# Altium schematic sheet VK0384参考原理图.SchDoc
size A4
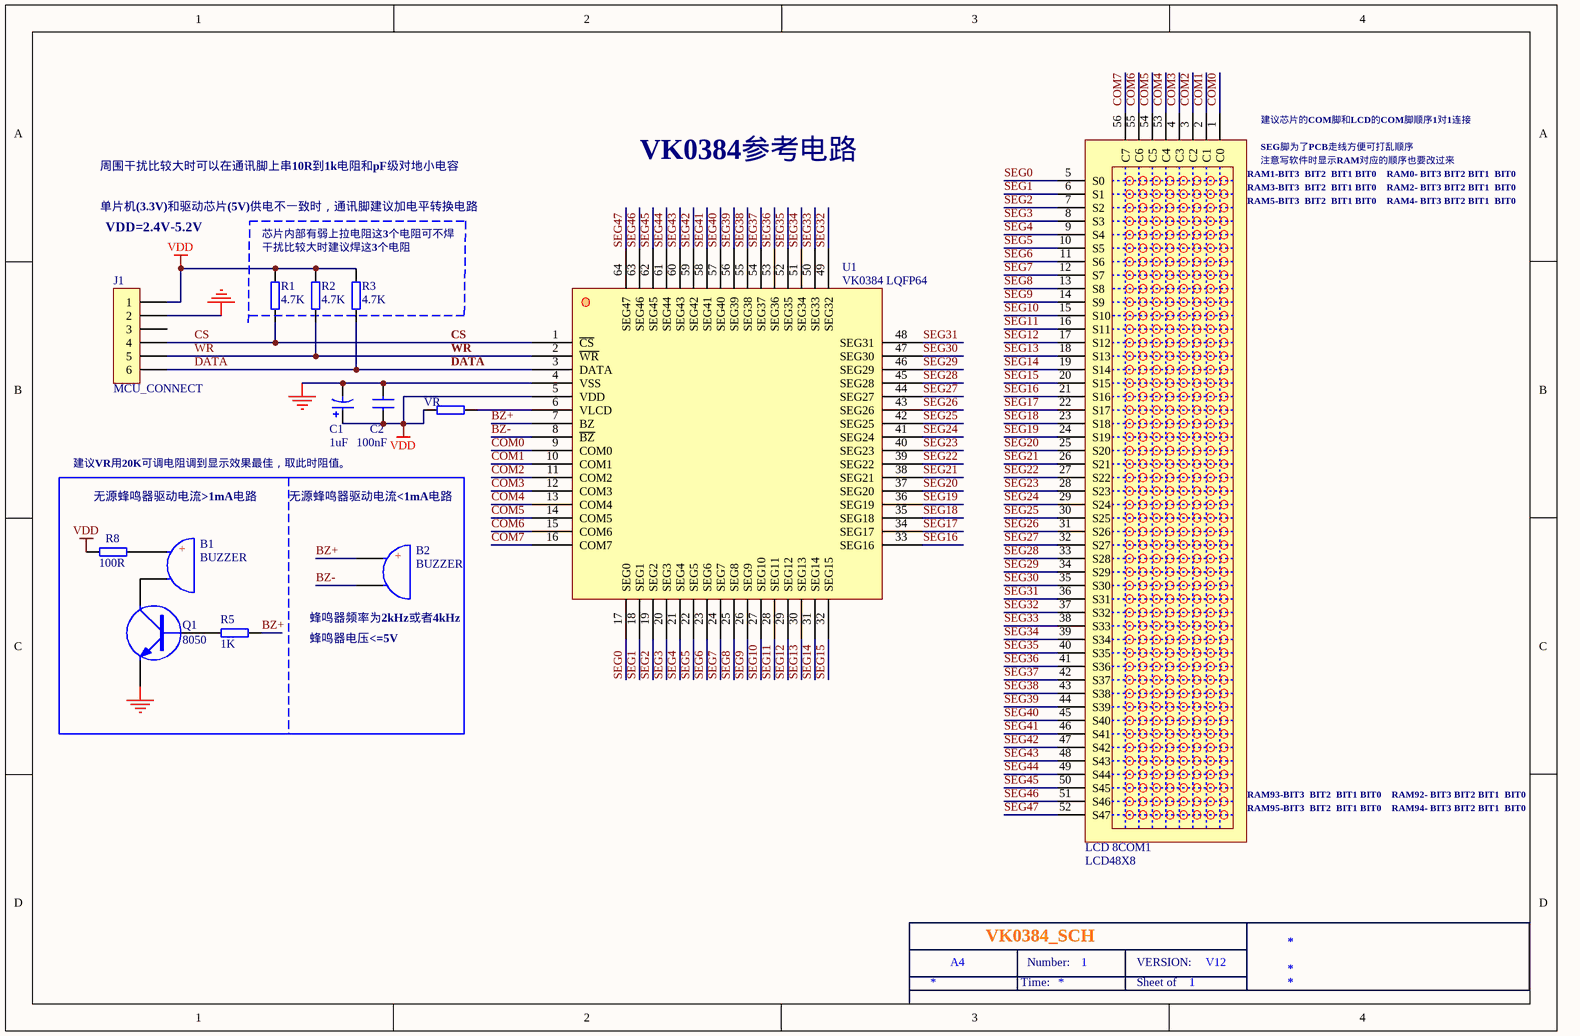
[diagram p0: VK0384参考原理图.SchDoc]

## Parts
B1  BUZZER  [BUZZER-12]
B2  BUZZER  [BUZZER-12]
C1  1uF  [1206-C]
C2  100nF  [0603-C]
J1  MCU_CONNECT
LCD_8COM1  LCD48X8
Q1  8050  [SOT-23]
R1  4.7K  [0603-R]
R2  4.7K  [0603-R]
R3  4.7K  [0603-R]
R5  1K  [0603-R]
R8  100R  [0603-R]
U1  VK0384 LQFP64
VR  (no value)  [0603-R]

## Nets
GND: C1.2 C2.2 J1.2 Q1.2 U1.4(VSS)
VDD: C1.1 C2.1 J1.1 R1.1 R2.1 R3.1 R8.2 U1.5(VDD) VR.1
BZ+: B2.1 R5.2 U1.7(BZ)
BZ-: B2.2 U1.8(~{BZ})
COM0: LCD_8COM1.1(C0) U1.9(COM0)
COM1: LCD_8COM1.2(C1) U1.10(COM1)
COM2: LCD_8COM1.3(C2) U1.11(COM2)
COM3: LCD_8COM1.4(C3) U1.12(COM3)
COM4: LCD_8COM1.53(C4) U1.13(COM4)
COM5: LCD_8COM1.54(C5) U1.14(COM5)
COM6: LCD_8COM1.55(C6) U1.15(COM6)
COM7: LCD_8COM1.56(C7) U1.16(COM7)
CS: J1.4 R1.2 U1.1(~{CS})
DATA: J1.6 R3.2 U1.3(DATA)
SEG0: LCD_8COM1.5(S0) U1.17(SEG0)
SEG1: LCD_8COM1.6(S1) U1.18(SEG1)
SEG2: LCD_8COM1.7(S2) U1.19(SEG2)
SEG3: LCD_8COM1.8(S3) U1.20(SEG3)
SEG4: LCD_8COM1.9(S4) U1.21(SEG4)
SEG5: LCD_8COM1.10(S5) U1.22(SEG5)
SEG6: LCD_8COM1.11(S6) U1.23(SEG6)
SEG7: LCD_8COM1.12(S7) U1.24(SEG7)
SEG8: LCD_8COM1.13(S8) U1.25(SEG8)
SEG9: LCD_8COM1.14(S9) U1.26(SEG9)
SEG10: LCD_8COM1.15(S10) U1.27(SEG10)
SEG11: LCD_8COM1.16(S11) U1.28(SEG11)
SEG12: LCD_8COM1.17(S12) U1.29(SEG12)
SEG13: LCD_8COM1.18(S13) U1.30(SEG13)
SEG14: LCD_8COM1.19(S14) U1.31(SEG14)
SEG15: LCD_8COM1.20(S15) U1.32(SEG15)
SEG16: LCD_8COM1.21(S16) U1.33(SEG16)
SEG17: LCD_8COM1.22(S17) U1.34(SEG17)
SEG18: LCD_8COM1.23(S18) U1.35(SEG18)
SEG19: LCD_8COM1.24(S19) U1.36(SEG19)
SEG20: LCD_8COM1.25(S20) U1.37(SEG20)
SEG21: LCD_8COM1.26(S21) U1.38(SEG21)
SEG22: LCD_8COM1.27(S22) U1.39(SEG22)
SEG23: LCD_8COM1.28(S23) U1.40(SEG23)
SEG24: LCD_8COM1.29(S24) U1.41(SEG24)
SEG25: LCD_8COM1.30(S25) U1.42(SEG25)
SEG26: LCD_8COM1.31(S26) U1.43(SEG26)
SEG27: LCD_8COM1.32(S27) U1.44(SEG27)
SEG28: LCD_8COM1.33(S28) U1.45(SEG28)
SEG29: LCD_8COM1.34(S29) U1.46(SEG29)
SEG30: LCD_8COM1.35(S30) U1.47(SEG30)
SEG31: LCD_8COM1.36(S31) U1.48(SEG31)
SEG32: LCD_8COM1.37(S32) U1.49(SEG32)
SEG33: LCD_8COM1.38(S33) U1.50(SEG33)
SEG34: LCD_8COM1.39(S34) U1.51(SEG34)
SEG35: LCD_8COM1.40(S35) U1.52(SEG35)
SEG36: LCD_8COM1.41(S36) U1.53(SEG36)
SEG37: LCD_8COM1.42(S37) U1.54(SEG37)
SEG38: LCD_8COM1.43(S38) U1.55(SEG38)
SEG39: LCD_8COM1.44(S39) U1.56(SEG39)
SEG40: LCD_8COM1.45(S40) U1.57(SEG40)
SEG41: LCD_8COM1.46(S41) U1.58(SEG41)
SEG42: LCD_8COM1.47(S42) U1.59(SEG42)
SEG43: LCD_8COM1.48(S43) U1.60(SEG43)
SEG44: LCD_8COM1.49(S44) U1.61(SEG44)
SEG45: LCD_8COM1.50(S45) U1.62(SEG45)
SEG46: LCD_8COM1.51(S46) U1.63(SEG46)
SEG47: LCD_8COM1.52(S47) U1.64(SEG47)
WR: J1.5 R2.2 U1.2(~{WR})
NetB1_1: B1.1 R8.1
NetB1_2: B1.2 Q1.3
NetQ1_1: Q1.1 R5.1
NetU1_6: U1.6(VLCD) VR.2

Not connected (* = marked no-connect by the designer): J1 3

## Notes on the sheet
- 周围干扰比较大时可以在通讯脚上串10R到1k电阻和pF级对地小电容
- VK0384参考电路
- (near LCD_8COM1) RAM1-BIT3  BIT2  BIT1 BIT0    RAM0- BIT3 BIT2 BIT1  BIT0
- (near LCD_8COM1) 建议芯片的COM脚和LCD的COM脚顺序1对1连接
- (near LCD_8COM1) SEG脚为了PCB走线方便可打乱顺序
- (near LCD_8COM1) 注意写软件时显示RAM对应的顺序也要改过来
- 单片机(3.3V)和驱动芯片(5V)供电不一致时，通讯脚建议加电平转换电路
- VDD=2.4V-5.2V
- 芯片内部有弱上拉电阻这3个电阻可不焊
- 干扰比较大时建议焊这3个电阻
- (near LCD_8COM1) RAM3-BIT3  BIT2  BIT1 BIT0    RAM2- BIT3 BIT2 BIT1  BIT0
- (near LCD_8COM1) RAM5-BIT3  BIT2  BIT1 BIT0    RAM4- BIT3 BIT2 BIT1  BIT0
- CS
- WR
- (near VR) DATA
- 建议VR用20K可调电阻调到显示效果最佳，取此时阻值。
- 无源蜂鸣器驱动电流>1mA电路
- 无源蜂鸣器驱动电流<1mA电路
- (near B2) 蜂鸣器频率为2kHz或者4kHz
- 蜂鸣器电压<=5V
- (near LCD_8COM1) RAM93-BIT3  BIT2  BIT1 BIT0    RAM92- BIT3 BIT2 BIT1  BIT0
- (near LCD_8COM1) RAM95-BIT3  BIT2  BIT1 BIT0    RAM94- BIT3 BIT2 BIT1  BIT0
- A4
- VK0384_SCH
- Time:
- Number:
- 1
- Sheet of
- VERSION:
- V12

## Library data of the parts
C1 = ECAP: Bi-Polar Capacitor
C2 = CAP: Capacitor
J1 = CON6: Connector
LCD_8COM1 = LCD 48X8
Q1 = NPN-1: NPN Transistor
R1-R3 R5 R8 VR = RES: Resistor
